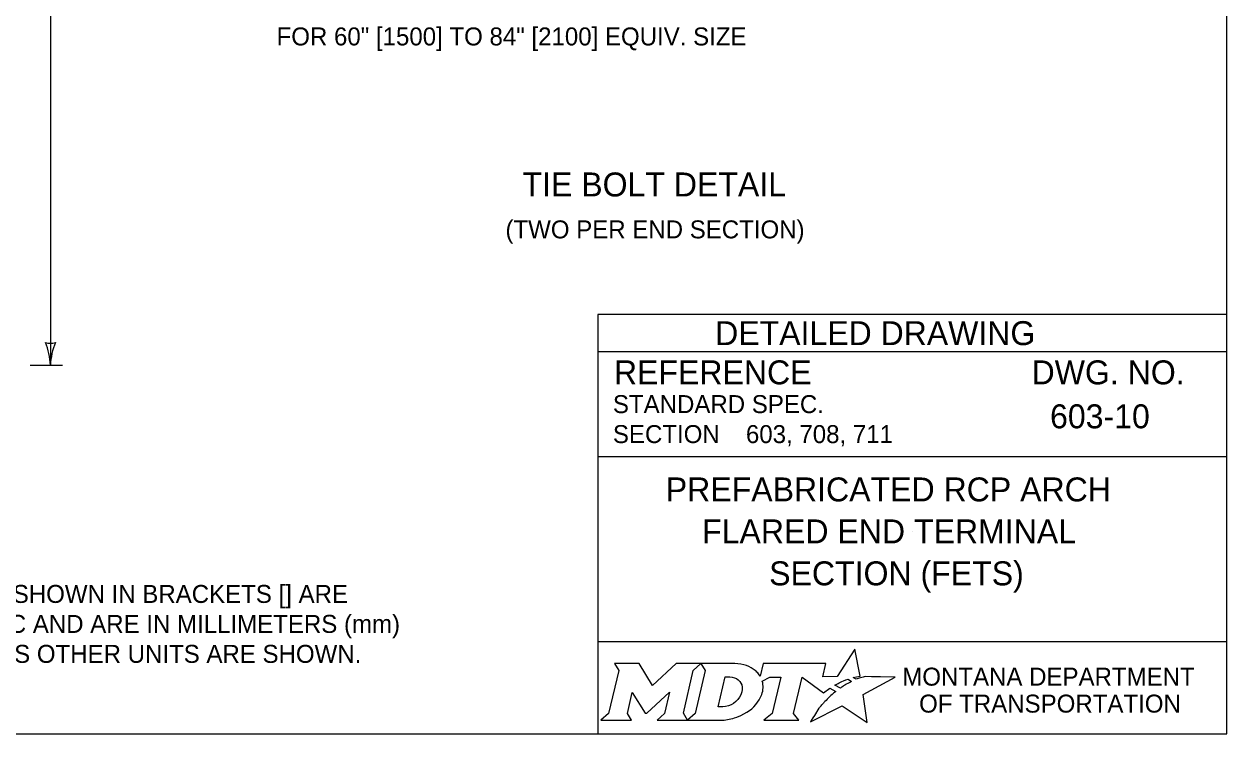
# Model space of a CAD drawing. Extents: x 49991.4 to 50021, y 49987.6 to 50011.4.
# Drawn here: x 50004.599 to 50008.615, y 50000.062 to 50002.431 of the extents above; entities that cross this region are included whole.
import ezdxf

# ---------------------------------------------------------------- set-up
doc = ezdxf.new("R2010")
doc.units = 0
for name, color, linetype in [('Level 1', 7, 'Continuous'), ('Level 2', 7, 'Continuous'), ('Level 3', 7, 'Continuous')]:
    doc.layers.add(name, color=color, linetype=linetype)

msp = doc.modelspace()

# ---------------------------------------------------------------- linework, layer by layer
at = {"layer": 'Level 1'}
msp.add_lwpolyline([(50008.6146, 50011.2628), (50000.3356, 50011.2628), (50000.3356, 50000.0624), (50008.6146, 50000.0624)], close=True, dxfattribs=at)
at = {"layer": 'Level 2'}
for p, q in [((50008.6146, 50001.4624), (50006.5146, 50001.4624)), ((50006.5146, 50001.4624), (50006.5146, 50000.0624)), ((50008.6146, 50001.3374), (50006.5146, 50001.3374)), ((50008.2507, 50001.1223), (50008.2507, 50001.1223)), ((50007.0089, 50001.0629), (50007.0089, 50001.0629)), ((50008.6146, 50000.9874), (50006.5146, 50000.9874)), ((50007.5646, 50000.7383), (50007.5646, 50000.7383)), ((50008.6146, 50000.3693), (50006.5146, 50000.3693))]:
    msp.add_line(p, q, dxfattribs=at)
for points in [[(50007.3771, 50000.2447), (50007.3668, 50000.2503), (50007.3784, 50000.2531), (50007.39, 50000.2551), (50007.3726, 50000.3452), (50007.3131, 50000.2539), (50007.2658, 50000.2532), (50007.2761, 50000.2973), (50007.0669, 50000.2974), (50007.0568, 50000.2549), (50007.051, 50000.2632)], [(50006.5701, 50000.2974), (50006.5842, 50000.274), (50006.5507, 50000.1307), (50006.525, 50000.1082), (50006.6266, 50000.1082), (50006.6131, 50000.131), (50006.6293, 50000.2011), (50006.673, 50000.1321), (50006.6783, 50000.1321), (50006.7534, 50000.2016), (50006.737, 50000.1305), (50006.7123, 50000.1085), (50006.8139, 50000.1085), (50006.8001, 50000.1318), (50006.8333, 50000.2742)], [(50006.8333, 50000.2742), (50006.8586, 50000.2974), (50006.7762, 50000.2974), (50006.6966, 50000.2244), (50006.6521, 50000.2971), (50006.5701, 50000.2974)], [(50006.9722, 50000.2974), (50006.8586, 50000.2974), (50006.8733, 50000.2745), (50006.8394, 50000.1307), (50006.8139, 50000.1085), (50006.9245, 50000.1085)], [(50006.9962, 50000.2107), (50006.995, 50000.2026), (50006.9918, 50000.1933), (50006.9876, 50000.1851), (50006.982, 50000.1776), (50006.9755, 50000.1707), (50006.9676, 50000.1644), (50006.9593, 50000.1597), (50006.9502, 50000.1558), (50006.9411, 50000.1535), (50006.9319, 50000.1526), (50006.916, 50000.1526), (50006.9396, 50000.2526), (50006.9556, 50000.2526), (50006.9632, 50000.252), (50006.9708, 50000.2501), (50006.9774, 50000.2471), (50006.9835, 50000.2429), (50006.9883, 50000.2379), (50006.992, 50000.2319), (50006.9947, 50000.2257), (50006.9963, 50000.2183), (50006.9963, 50000.2153), (50006.9962, 50000.2107)], [(50007.0636, 50000.2383), (50007.0882, 50000.2514), (50007.1251, 50000.2514), (50007.0965, 50000.1309), (50007.069, 50000.1082), (50007.1852, 50000.1082), (50007.1682, 50000.1311), (50007.1964, 50000.2513), (50007.2677, 50000.1996), (50007.2888, 50000.2147), (50007.3085, 50000.2038)], [(50007.2527, 50000.1479), (50007.2374, 50000.1235), (50007.2327, 50000.116), (50007.2269, 50000.1074), (50007.2246, 50000.1031), (50007.3299, 50000.1562), (50007.4138, 50000.1011), (50007.4007, 50000.1938), (50007.5076, 50000.2522), (50007.4583, 50000.253), (50007.4282, 50000.2534), (50007.4074, 50000.2537), (50007.4006, 50000.2522), (50007.3957, 50000.251), (50007.3873, 50000.2487), (50007.3771, 50000.2447)], [(50007.3267, 50000.2171), (50007.3243, 50000.2154), (50007.306, 50000.225), (50007.3163, 50000.2307), (50007.3204, 50000.2329), (50007.329, 50000.2369), (50007.3347, 50000.2395), (50007.3426, 50000.2425), (50007.3499, 50000.2452), (50007.3617, 50000.2378), (50007.3577, 50000.2357), (50007.3531, 50000.2332), (50007.3489, 50000.231), (50007.3439, 50000.2281), (50007.342, 50000.227), (50007.3393, 50000.2254), (50007.3368, 50000.224), (50007.3345, 50000.2224), (50007.3319, 50000.2206), (50007.3292, 50000.2188), (50007.3267, 50000.2171)], [(50007.2666, 50000.164), (50007.2666, 50000.164)], [(50006.9702, 50000.1158), (50006.9786, 50000.1184), (50006.9916, 50000.1238), (50007.012, 50000.1348)]]:
    msp.add_lwpolyline(points, dxfattribs=at)
for centre, radius, start, end in [((50006.9953, 50000.219), 0.0709, 339.5329, 15.8582), ((50006.9513, 50000.2363), 0.1183, 300.9103, 339.1383)]:
    msp.add_arc(centre, radius, start, end, dxfattribs=at)
for centre, major_axis, ratio, start_param, end_param in [((50006.9701, 50000.25), (0.0834, -0.0037), 0.568097, 0.61298, 1.570796), ((50007.0257, 50000.2573), (0.0361, -0.0295), 0.469099, 1.225588, 1.570796), ((50007.2974, 50000.1941), (-0.0112, -0.0097), 0.021651, 3.157348, 6.283185), ((50007.2597, 50000.1559), (-0.00694, -0.00806), 0.008222, 0, 3.137361), ((50007.2764, 50000.1742), (-0.0098, -0.0102), 0.016458, 3.141593, 6.279097), ((50006.9248, 50000.2568), (0, 0.1484), 0.987302, 3.139398, 3.456847)]:
    msp.add_ellipse(centre, major_axis=major_axis, ratio=ratio, start_param=start_param, end_param=end_param, dxfattribs=at)
at = {"layer": 'Level 3'}
for p, q in [((50004.6872, 50003.6459), (50004.6872, 50001.2929)), ((50004.6192, 50001.2929), (50004.7272, 50001.2929))]:
    msp.add_line(p, q, dxfattribs=at)
for centre, radius, start, end in [((50004.6872, 50001.4211), 0.0548, 252.1388, 287.8612), ((50004.4545, 50001.2814), 0.233, 2.8273, 22.0772), ((50004.9094, 50001.2838), 0.2223, 157.456, 177.6395)]:
    msp.add_arc(centre, radius, start, end, dxfattribs=at)

# ---------------------------------------------------------------- texts
at = {"layer": 'Level 2'}
for s, height, p in [('FOR 60" [1500] TO 84" [2100] EQUIV. SIZE ', 0.06, (50005.4422, 50002.36)), ('TIE BOLT DETAIL', 0.08, (50006.263, 50001.856)), ('(TWO PER END SECTION)', 0.06, (50006.2062, 50001.7161)), ('DETAILED DRAWING', 0.0799, (50006.9063, 50001.3599)), ('REFERENCE', 0.08, (50006.5682, 50001.229)), ('DWG. NO.', 0.08, (50007.9624, 50001.229)), ('STANDARD SPEC.', 0.06, (50006.5649, 50001.133)), ('603-10', 0.08, (50008.0241, 50001.0823)), ('SECTION', 0.06, (50006.5649, 50001.033)), ('603, 708, 711', 0.06, (50007.0089, 50001.0329)), ('PREFABRICATED RCP ARCH', 0.08, (50006.7414, 50000.8383)), ('FLARED END TERMINAL', 0.08, (50006.8626, 50000.6983)), ('SECTION (FETS)', 0.08, (50007.0865, 50000.5583)), ('UNITS SHOWN IN BRACKETS [] ARE ', 0.06, (50004.2986, 50000.4996)), ('METRIC AND ARE IN MILLIMETERS (mm) ', 0.06, (50004.2986, 50000.3996)), ('UNLESS OTHER UNITS ARE SHOWN.', 0.06, (50004.2986, 50000.2996)), ('MONTANA DEPARTMENT', 0.06, (50007.5308, 50000.2236)), ('OF TRANSPORTATION', 0.06, (50007.587, 50000.1336))]:
    msp.add_text(s, height=height, dxfattribs=at).set_placement(p)

doc.saveas('drawing.dxf')
